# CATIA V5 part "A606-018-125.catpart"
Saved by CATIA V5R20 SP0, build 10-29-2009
Part number: A606-018-125
Source: Unknown
Property "ARTICLENO": "A606-018-125"
Property "BOMINFO": "A606-018-125"
Property "CODE": "A606-018-125"
Property "HOLES": "2"
Property "L": "125.000"
Property "L1": "25.000"
Property "L2": "75.000"
Property "LINA": "A606-018-125"
Property "NB": "A606-018-125"
Property "NBSYN": "$CODE."
Property "NN": "A606"
Property "NT": "Wear Plates, self-lubricating"
Property "SCREW": "2xM6"
Property "SUPPLIER": "CF"
Property "W": "18.000"
Bounding box of the stored display mesh (mm): x -9 to 9, y -5 to 5, z -62.5 to 62.5
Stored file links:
  C:\Users\Utente\Desktop\3D files A606\A606-018-125.catpart

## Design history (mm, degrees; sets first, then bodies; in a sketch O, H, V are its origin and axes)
Body1 "Geometry.1" (main body)
  Solid1 "A606-018-125.catpart": solid without history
